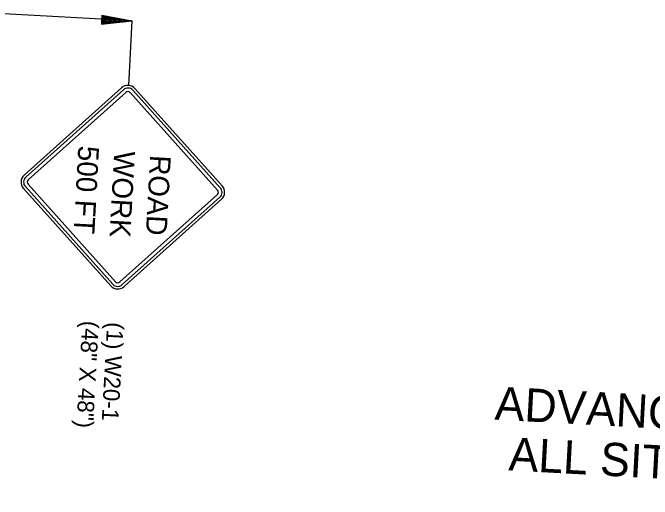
# Model space of a CAD drawing. Extents: x 879461 to 881100, y 1566470 to 1567598.
# Drawn here: x 879979.1 to 880209.8, y 1566972.5 to 1567148 of the extents above; entities that cross this region are included whole.
import ezdxf

# ---------------------------------------------------------------- set-up
doc = ezdxf.new("R2010")
doc.units = 0
for name, color, linetype in [('P_TC_Signs_Temporary', 7, 'Continuous'), ('R_Annotation', 7, 'Continuous'), ('R_Draft', 7, 'Continuous')]:
    doc.layers.add(name, color=color, linetype=linetype)

msp = doc.modelspace()

# ---------------------------------------------------------------- linework, layer by layer
at = {"layer": 'P_TC_Signs_Temporary'}
for p, q in [((879983.16, 1567089.39), (880018.34, 1567120.94)), ((879983.79, 1567088.69), (880018.97, 1567120.24)), ((880023.11, 1567120.68), (880054.65, 1567085.5)), ((879984.67, 1567087.71), (880019.84, 1567119.26)), ((880021.43, 1567119.18), (880052.98, 1567084)), ((880022.41, 1567120.05), (880053.95, 1567084.88)), ((880016.13, 1567050.95), (879984.58, 1567086.13)), ((880014.45, 1567049.45), (879982.9, 1567084.62)), ((880015.15, 1567050.07), (879983.6, 1567085.25)), ((880052.89, 1567082.41), (880017.72, 1567050.86)), ((880053.77, 1567081.43), (880018.59, 1567049.89)), ((880054.39, 1567080.74), (880019.22, 1567049.19))]:
    msp.add_line(p, q, dxfattribs=at)
for centre, radius, start, end in [((880020.59, 1567118.42), 3.38, 41.8871, 131.8871), ((880020.59, 1567118.42), 2.44, 41.8871, 131.8871), ((880020.59, 1567118.42), 1.12, 41.8871, 131.8871), ((879985.42, 1567086.88), 3.38, 131.8871, 221.8871), ((879985.42, 1567086.88), 2.44, 131.8871, 221.8871), ((879985.42, 1567086.88), 1.13, 131.8871, 221.8871), ((880052.14, 1567083.25), 1.13, 311.8871, 41.8871), ((880052.14, 1567083.25), 2.44, 311.8871, 41.8871), ((880052.14, 1567083.25), 3.38, 311.8871, 41.8871), ((880016.96, 1567051.7), 1.12, 221.8871, 311.8871), ((880016.96, 1567051.7), 3.38, 221.8871, 311.8871), ((880016.96, 1567051.7), 2.44, 221.8871, 311.8871)]:
    msp.add_arc(centre, radius, start, end, dxfattribs=at)
at = {"layer": 'R_Draft'}
for p, q in [((880022.04, 1567145.06), (879922.19, 1567150.49)), ((880011.23, 1567147.1), (880011.11, 1567143.84)), ((880011.18, 1567145.73), (880012.89, 1567145.4)), ((880011.19, 1567146), (880014.7, 1567145.34)), ((880011.2, 1567146.28), (880016.55, 1567145.26)), ((880011.21, 1567146.55), (880018.36, 1567145.2)), ((880011.22, 1567146.83), (880020.22, 1567145.12)), ((880011.23, 1567147.1), (880022.04, 1567145.06)), ((880011.11, 1567143.84), (880022.04, 1567145.06)), ((880011.12, 1567144.11), (880020.22, 1567145.12)), ((880011.13, 1567144.39), (880018.36, 1567145.2)), ((880011.14, 1567144.66), (880016.55, 1567145.26)), ((880011.15, 1567144.94), (880014.7, 1567145.34)), ((880011.16, 1567145.22), (880012.89, 1567145.4)), ((880022.04, 1567145.06), (880020.78, 1567121.79))]:
    msp.add_line(p, q, dxfattribs=at)

# ---------------------------------------------------------------- texts
at = {"layer": 'P_TC_Signs_Temporary'}
for s, p in [('500 FT ', (880002.74, 1567100.16)), ('WORK', (880015.68, 1567098.24)), (' ROAD ', (880028.79, 1567099.56))]:
    msp.add_text(s, height=7.5, rotation=266.8871, dxfattribs=at).set_placement(p)
at = {"layer": 'R_Annotation'}
for s, height, rotation, p in [('(48" X 48")', 6, 266.8871, (880004.14, 1567036.95)), ('(1) W20-1', 6, 266.8871, (880013.13, 1567036.46)), ('ADVANCE WARNING DETAILS', 12, 356.8871, (880152.79, 1567001.17)), ('ALL SITES - ALL STAGES', 12, 356.8871, (880157.8, 1566982.87))]:
    msp.add_text(s, height=height, rotation=rotation, dxfattribs=at).set_placement(p)

doc.saveas('drawing.dxf')
